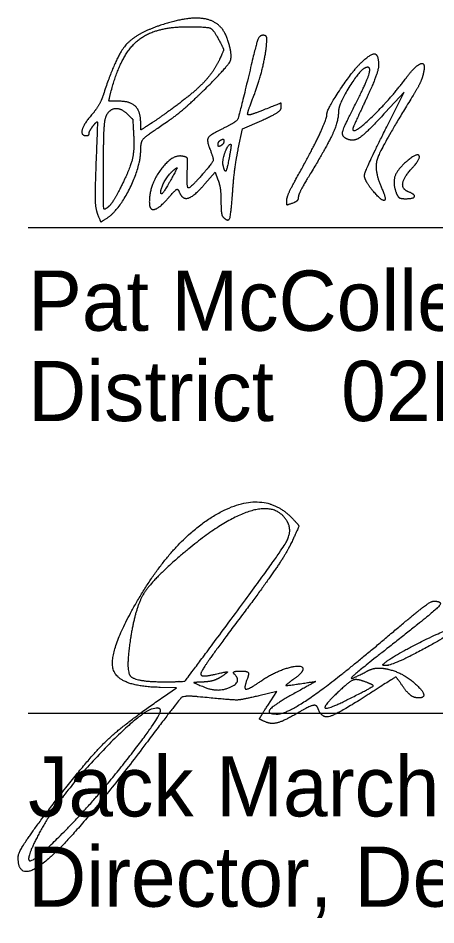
# Model space of a CAD drawing. Extents: x 0 to 40.2, y 0 to 22.
# Drawn here: x 24.504 to 25.477, y 6.637 to 8.746 of the extents above; entities that cross this region are included whole.
import ezdxf

# ---------------------------------------------------------------- set-up
doc = ezdxf.new("R2010")
doc.units = 0
doc.layers.add('GM_X_Adjacent_County', color=7, linetype='Continuous')
doc.layers.add('GM_X_Adjacent_County_Text', color=7, linetype='Continuous')

msp = doc.modelspace()

# ---------------------------------------------------------------- linework, layer by layer
at = {"layer": 'GM_X_Adjacent_County'}
for p, q in [((24.5279, 8.259), (28.0279, 8.259)), ((24.5279, 7.1296), (28.0279, 7.1296))]:
    msp.add_line(p, q, dxfattribs=at)
at = {"layer": 'GM_X_Adjacent_County_Text'}
for p, q in [((25.3839, 8.341), (25.3839, 8.341)), ((25.1298, 8.3231), (25.1298, 8.3231)), ((24.9902, 7.3347), (24.9902, 7.3347)), ((25.3555, 7.2448), (25.3555, 7.2448)), ((25.3107, 7.2032), (25.3107, 7.2032))]:
    msp.add_line(p, q, dxfattribs=at)
for points in [[(25.3624, 8.4933), (25.4028, 8.574), (25.3588, 8.5264)], [(25.0169, 8.4422), (25.0265, 8.4883), (25.0715, 8.5082)], [(24.9391, 8.3604), (24.9628, 8.388), (24.9696, 8.37)], [(24.8425, 7.1677), (24.8732, 7.1889), (24.8354, 7.1896)], [(25.0855, 7.1479), (25.1067, 7.1802), (25.0649, 7.1701)]]:
    msp.add_lwpolyline(points, dxfattribs=at)
for points in [[(24.9918, 8.6968), (24.9786, 8.7365), (24.9017, 8.7518), (24.8329, 8.7283)], [(24.8329, 8.7283), (24.7758, 8.7088), (24.7306, 8.6534), (24.7031, 8.569)], [(24.7194, 8.5702), (24.7414, 8.6579), (24.8197, 8.7261), (24.8985, 8.7261)], [(24.8985, 8.7261), (24.9444, 8.7261), (24.9594, 8.7193), (24.9733, 8.6924)], [(24.9376, 8.5793), (24.9919, 8.6329), (25.0042, 8.6595), (24.9918, 8.6968)], [(24.9733, 8.6924), (24.9828, 8.6742), (24.9826, 8.6703), (24.972, 8.6476)], [(25.0748, 8.7061), (25.0657, 8.7061), (25.0578, 8.6836), (25.0395, 8.6061)], [(25.0524, 8.5641), (25.066, 8.5988), (25.0832, 8.6737), (25.0832, 8.6983)], [(25.0832, 8.6983), (25.0832, 8.7026), (25.0794, 8.7061), (25.0748, 8.7061)], [(24.972, 8.6476), (24.9586, 8.6192), (24.9104, 8.5699), (24.8606, 8.5337)], [(25.3023, 8.642), (25.3255, 8.6641), (25.3432, 8.6616), (25.3432, 8.6362)], [(25.2232, 8.5235), (25.2232, 8.5338), (25.2832, 8.6238), (25.3023, 8.642)], [(25.3142, 8.6311), (25.3003, 8.6268), (25.2498, 8.5453), (25.2498, 8.5272)], [(25.2876, 8.5423), (25.3147, 8.5947), (25.3268, 8.6349), (25.3142, 8.6311)], [(25.3432, 8.6362), (25.3432, 8.6269), (25.3297, 8.5903), (25.3132, 8.555)], [(25.4052, 8.604), (25.4304, 8.6375), (25.4539, 8.6434), (25.4467, 8.6144)], [(25.0395, 8.6061), (25.0187, 8.5177), (25.0121, 8.5042), (24.9824, 8.4898)], [(25.2832, 8.4885), (25.2832, 8.4738), (25.3667, 8.5529), (25.4052, 8.604)], [(25.4467, 8.6144), (25.4443, 8.6043), (25.4339, 8.5826), (25.4236, 8.5661)], [(24.7031, 8.569), (24.6984, 8.5546), (24.686, 8.5329), (24.6755, 8.5209)], [(24.7386, 8.5528), (24.7165, 8.5528), (24.7153, 8.5539), (24.7194, 8.5702)], [(24.8532, 8.5065), (24.8715, 8.5189), (24.9095, 8.5516), (24.9376, 8.5793)], [(25.039, 8.5214), (25.0377, 8.5227), (25.0437, 8.5419), (25.0524, 8.5641)], [(25.4236, 8.5661), (25.3496, 8.4467), (25.3314, 8.3925), (25.3509, 8.3497)], [(24.7898, 8.5017), (24.7898, 8.5286), (24.7656, 8.5528), (24.7386, 8.5528)], [(25.1165, 8.5371), (25.1165, 8.5486), (25.1167, 8.5486), (25.0759, 8.5325)], [(25.2715, 8.4642), (25.2573, 8.4693), (25.2622, 8.4934), (25.2876, 8.5423)], [(25.3132, 8.555), (25.2967, 8.5197), (25.2832, 8.4898), (25.2832, 8.4885)], [(24.6755, 8.5209), (24.6569, 8.4994), (24.65, 8.4728), (24.6632, 8.4728)], [(24.7032, 8.4024), (24.7032, 8.4617), (24.7061, 8.5125), (24.7101, 8.5199)], [(24.7101, 8.5199), (24.7184, 8.5355), (24.7449, 8.5368), (24.7594, 8.5223)], [(24.7594, 8.5223), (24.7716, 8.5101), (24.7711, 8.5116), (24.7733, 8.4728)], [(24.8606, 8.5337), (24.8418, 8.5201), (24.8182, 8.5038), (24.8082, 8.4974)], [(25.0759, 8.5325), (25.0569, 8.525), (25.0403, 8.52), (25.039, 8.5214)], [(25.0715, 8.5082), (25.0962, 8.5191), (25.1165, 8.5321), (25.1165, 8.5371)], [(25.151, 8.3715), (25.1874, 8.4367), (25.2232, 8.5121), (25.2232, 8.5235)], [(25.2498, 8.5272), (25.2498, 8.5062), (25.2229, 8.4473), (25.1842, 8.3836)], [(25.3588, 8.5264), (25.3143, 8.4784), (25.2868, 8.4588), (25.2715, 8.4642)], [(24.6798, 8.4965), (24.6886, 8.5081), (24.6893, 8.4988), (24.6857, 8.4094)], [(24.7898, 8.4399), (24.7898, 8.4589), (24.8031, 8.4729), (24.8532, 8.5065)], [(24.8082, 8.4974), (24.79, 8.4859), (24.7898, 8.486), (24.7898, 8.5017)], [(24.6632, 8.4728), (24.6668, 8.4728), (24.6698, 8.4752), (24.6698, 8.4782)], [(24.6698, 8.4782), (24.6698, 8.4811), (24.6743, 8.4894), (24.6798, 8.4965)], [(24.9824, 8.4898), (24.9516, 8.4749), (24.9426, 8.4617), (24.9502, 8.4428)], [(25.3319, 8.3423), (25.3082, 8.3698), (25.3134, 8.3957), (25.3624, 8.4933)], [(24.7733, 8.4728), (24.7753, 8.4371), (24.7641, 8.3941), (24.7411, 8.3485)], [(24.9698, 8.452), (24.9698, 8.4556), (24.9728, 8.4605), (24.9765, 8.4628)], [(24.9765, 8.4628), (24.9802, 8.465), (24.9832, 8.4639), (24.9832, 8.4602)], [(24.9832, 8.4602), (24.9832, 8.4565), (24.9802, 8.4517), (24.9765, 8.4494)], [(24.7116, 8.2812), (24.7395, 8.2997), (24.7898, 8.4018), (24.7898, 8.4399)], [(24.9502, 8.4428), (24.9596, 8.4195), (24.957, 8.4099), (24.9348, 8.3843)], [(24.9765, 8.4494), (24.9728, 8.4472), (24.9698, 8.4483), (24.9698, 8.452)], [(24.9816, 8.4039), (24.9792, 8.4145), (24.9929, 8.4528), (24.9991, 8.4528)], [(24.9991, 8.4528), (25.0004, 8.4528), (24.9992, 8.4406), (24.9964, 8.4258)], [(25.0036, 8.34), (25.0057, 8.3708), (25.0117, 8.4168), (25.0169, 8.4422)], [(24.8875, 8.4248), (24.8629, 8.4299), (24.8098, 8.3573), (24.8098, 8.3186)], [(24.8982, 8.3908), (24.8995, 8.4168), (24.8977, 8.4227), (24.8875, 8.4248)], [(24.9964, 8.4258), (24.9907, 8.3945), (24.9855, 8.3867), (24.9816, 8.4039)], [(25.4203, 8.396), (25.4427, 8.4202), (25.4319, 8.4331), (25.4073, 8.4115)], [(24.6857, 8.4094), (24.683, 8.342), (24.6842, 8.3032), (24.6892, 8.2904)], [(24.7137, 8.3065), (24.7042, 8.2986), (24.7032, 8.3079), (24.7032, 8.4024)], [(24.8365, 8.3418), (24.8365, 8.3513), (24.8557, 8.3838), (24.8667, 8.3929)], [(24.8667, 8.3929), (24.875, 8.3998), (24.8741, 8.3956), (24.8632, 8.3758)], [(25.4073, 8.4115), (25.3865, 8.3934), (25.3761, 8.3621), (25.3839, 8.341)], [(25.4132, 8.3418), (25.3977, 8.3478), (25.4013, 8.3755), (25.4203, 8.396)], [(24.8632, 8.3758), (24.8476, 8.3478), (24.8365, 8.3335), (24.8365, 8.3418)], [(24.9348, 8.3843), (24.9053, 8.3502), (24.8962, 8.3519), (24.8982, 8.3908)], [(25.1298, 8.3231), (25.1298, 8.3288), (25.1394, 8.3506), (25.151, 8.3715)], [(25.1842, 8.3836), (25.169, 8.3586), (25.1565, 8.3342), (25.1565, 8.3295)], [(24.8791, 8.3424), (24.8864, 8.3233), (24.9146, 8.3318), (24.9391, 8.3604)], [(24.9696, 8.37), (24.9734, 8.36), (24.9765, 8.3376), (24.9765, 8.3201)], [(24.7411, 8.3485), (24.7318, 8.3302), (24.7195, 8.3113), (24.7137, 8.3065)], [(24.8552, 8.329), (24.8701, 8.346), (24.8763, 8.3494), (24.8791, 8.3424)], [(24.9811, 8.2837), (24.9933, 8.2715), (25.0002, 8.2887), (25.0036, 8.34)], [(25.1565, 8.3295), (25.1565, 8.3247), (25.1518, 8.319), (25.146, 8.3168)], [(25.3509, 8.3497), (25.3624, 8.3244), (25.3511, 8.32), (25.3319, 8.3423)], [(25.3839, 8.341), (25.3876, 8.3309), (25.3949, 8.3261), (25.4063, 8.3261)], [(25.4063, 8.3261), (25.4248, 8.3261), (25.429, 8.3358), (25.4132, 8.3418)], [(24.8098, 8.3186), (24.8098, 8.2984), (24.8331, 8.3038), (24.8552, 8.329)], [(24.9765, 8.3201), (24.9765, 8.3026), (24.9786, 8.2863), (24.9811, 8.2837)], [(25.146, 8.3168), (25.131, 8.3111), (25.1298, 8.3115), (25.1298, 8.3231)], [(24.6892, 8.2904), (24.6963, 8.2724), (24.6976, 8.2719), (24.7116, 8.2812)], [(24.7789, 7.3854), (24.8651, 7.5358), (25.0732, 7.6518), (25.1389, 7.5862)], [(25.1299, 7.577), (25.104, 7.619), (24.9779, 7.5778), (24.8825, 7.4962)], [(24.9902, 7.3347), (25.1115, 7.4981), (25.144, 7.5543), (25.1299, 7.577)], [(25.1389, 7.5862), (25.1577, 7.5674), (25.1577, 7.5623), (25.1394, 7.5239)], [(25.1394, 7.5239), (25.1284, 7.5009), (25.0767, 7.4254), (25.0245, 7.356)], [(24.8825, 7.4962), (24.8159, 7.4392), (24.7771, 7.3751), (24.766, 7.3038)], [(24.8354, 7.1896), (24.7375, 7.1913), (24.7141, 7.2724), (24.7789, 7.3854)], [(25.369, 7.3119), (25.4194, 7.3548), (25.4649, 7.39), (25.4701, 7.3901)], [(25.4701, 7.3901), (25.495, 7.3906), (25.4716, 7.365), (25.3857, 7.2977)], [(25.0245, 7.356), (24.9722, 7.2867), (24.9295, 7.226), (24.9295, 7.2212)], [(24.844, 7.2027), (24.8907, 7.2027), (24.8953, 7.2069), (24.9902, 7.3347)], [(25.3555, 7.2448), (25.3759, 7.2627), (25.5079, 7.3284), (25.5131, 7.3233)], [(25.5131, 7.3233), (25.5193, 7.3171), (25.3767, 7.2402), (25.359, 7.2402)], [(24.766, 7.3038), (24.7545, 7.2305), (24.776, 7.2027), (24.844, 7.2027)], [(25.1076, 7.1277), (25.1307, 7.1277), (25.2567, 7.2166), (25.369, 7.3119)], [(25.3857, 7.2977), (25.2925, 7.2247), (25.271, 7.2032), (25.315, 7.2267)], [(25.0736, 7.2071), (25.1025, 7.2269), (25.167, 7.2444), (25.167, 7.2325)], [(25.315, 7.2267), (25.3276, 7.2334), (25.3515, 7.2355), (25.3681, 7.2313)], [(25.359, 7.2402), (25.3542, 7.2402), (25.3526, 7.2423), (25.3555, 7.2448)], [(24.9295, 7.2212), (24.9295, 7.2164), (24.9449, 7.2161), (24.9638, 7.2205)], [(24.9795, 7.2158), (24.9692, 7.2088), (24.9495, 7.2027), (24.9357, 7.2021)], [(24.9399, 7.1895), (24.9698, 7.1775), (25.026, 7.2021), (25.0086, 7.2195)], [(24.9638, 7.2205), (24.9894, 7.2264), (24.9934, 7.2252), (24.9795, 7.2158)], [(25.0086, 7.2195), (25.004, 7.224), (25.0103, 7.2277), (25.0225, 7.2277)], [(25.0225, 7.2277), (25.037, 7.2277), (25.0422, 7.2213), (25.0375, 7.209)], [(25.167, 7.2325), (25.167, 7.228), (25.1572, 7.2171), (25.1453, 7.2084)], [(25.4011, 7.1899), (25.3843, 7.214), (25.3822, 7.2135), (25.3165, 7.1712)], [(25.3681, 7.2313), (25.4042, 7.2222), (25.4625, 7.1652), (25.4358, 7.1652)], [(24.9357, 7.2021), (24.9133, 7.2013), (24.9138, 7.1999), (24.9399, 7.1895)], [(25.0375, 7.209), (25.0285, 7.1857), (25.0414, 7.1851), (25.0736, 7.2071)], [(25.1453, 7.2084), (25.1264, 7.1946), (25.1284, 7.1933), (25.161, 7.1982)], [(25.161, 7.1982), (25.1977, 7.2038), (25.1976, 7.2035), (25.1522, 7.1784)], [(25.3107, 7.2032), (25.2935, 7.2095), (25.277, 7.2044), (25.2576, 7.1866)], [(25.2826, 7.1668), (25.329, 7.1905), (25.3325, 7.1951), (25.3107, 7.2032)], [(25.0649, 7.1701), (25.0246, 7.1604), (25.0023, 7.16), (24.9237, 7.1678)], [(25.1522, 7.1784), (25.1011, 7.1502), (25.0814, 7.1277), (25.1076, 7.1277)], [(25.3165, 7.1712), (25.2476, 7.1268), (25.2101, 7.1171), (25.202, 7.1414)], [(25.2576, 7.1866), (25.2133, 7.1461), (25.2246, 7.1372), (25.2826, 7.1668)], [(25.4358, 7.1652), (25.4262, 7.1652), (25.4106, 7.1763), (25.4011, 7.1899)], [(24.5916, 6.9255), (24.6692, 7.026), (24.7493, 7.1033), (24.8425, 7.1677)], [(24.9237, 7.1678), (24.8903, 7.1711), (24.8786, 7.1606), (24.8019, 7.059)], [(24.8354, 7.1385), (24.8145, 7.1594), (24.596, 6.9337), (24.5497, 6.8434)], [(24.6198, 6.8621), (24.6874, 6.9312), (24.8431, 7.1308), (24.8354, 7.1385)], [(25.0843, 7.1078), (25.0661, 7.1148), (25.0662, 7.1184), (25.0855, 7.1479)], [(25.1508, 7.1276), (25.1252, 7.1125), (25.0953, 7.1036), (25.0843, 7.1078)], [(25.202, 7.1414), (25.1991, 7.15), (25.1799, 7.1448), (25.1508, 7.1276)], [(24.8019, 7.059), (24.6496, 6.8569), (24.5045, 6.7283), (24.5045, 6.7953)], [(24.5045, 6.7953), (24.5045, 6.8049), (24.5437, 6.8635), (24.5916, 6.9255)], [(24.5497, 6.8434), (24.5184, 6.7824), (24.55, 6.7909), (24.6198, 6.8621)]]:
    msp.add_open_spline(points, degree=2, dxfattribs=at)

# ---------------------------------------------------------------- texts
for s, p in [('Pat McColley, P.E., S.I.', (24.5279, 8.019)), ('District       Deputy Director', (24.5279, 7.809)), ('              02', (24.5279, 7.809)), ('Jack Marchbanks, PhD', (24.5279, 6.8896)), ('Director, Department of Transportation', (24.5279, 6.6796))]:
    msp.add_text(s, height=0.14, dxfattribs=at).set_placement(p)

doc.saveas('drawing.dxf')
